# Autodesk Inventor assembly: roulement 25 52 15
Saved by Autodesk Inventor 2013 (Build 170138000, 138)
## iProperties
Created: 2012-12
Part Number: roulement 25 52 15
Document SubType Name: Assembly
Designer: jost thierry
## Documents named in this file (4)
- X:\Cours & TP\Jost.Thierry\02-01-TP02aRavoux\02-02-Dessin 3D\11 - Reducteur S37 SEW\roulement 25 52 15.iam
- X:\Cours & TP\Jost.Thierry\02-01-TP02aRavoux\02-02-Dessin 3D\11 - Reducteur S37 SEW\BI 25 52.ipt
- X:\Cours & TP\Jost.Thierry\02-01-TP02aRavoux\02-02-Dessin 3D\11 - Reducteur S37 SEW\BE 25 52.ipt
- X:\Cours & TP\Jost.Thierry\02-01-TP02aRavoux\02-02-Dessin 3D\11 - Reducteur S37 SEW\BILLE 25 52.ipt
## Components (10 placed, 3 different names)
1. BI 25 52:1
2. BE 25 52:1
3. BILLE 25 52:1
4. BILLE 25 52:2
5. BILLE 25 52:3
6. BILLE 25 52:4
7. BILLE 25 52:5
8. BILLE 25 52:6
9. BILLE 25 52:7
10. BILLE 25 52:8
